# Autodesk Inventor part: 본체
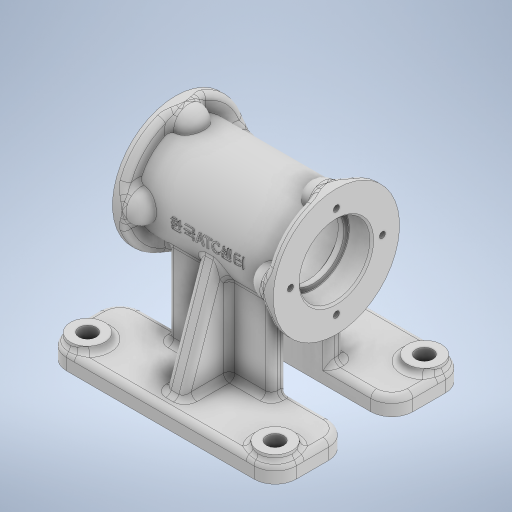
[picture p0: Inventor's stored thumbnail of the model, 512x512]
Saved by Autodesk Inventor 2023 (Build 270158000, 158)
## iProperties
Created: 2026-06
Part Number: 본체
Material: 일반
Document SubType Name: Modeling
Designer: home
Density: 1 g/cm^3
Appearance: 기본값
Author: home
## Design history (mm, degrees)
sketch "스케치1"
  geometry: L1 (0, 0)-(-75.914, 0); L2 (-42, 0)-(-42, 33); L3 (-42, 33)-(-37, 33); L4 (-37, 33)-(-37, 25); L5 (-37, 25)-(0, 25); L6 (0, 0)-(0, 52.72); L7 (37, 25)-(0, 25); L8 (37, 33)-(37, 25); L9 (42, 33)-(37, 33); L10 (42, 0)-(42, 33); L11 (-42, 18.5)-(-30, 18.5); L12 (-30, 18.5)-(-30, 16); L13 (-30, 16)-(-27, 16); L14 (-27, 16)-(-27, 20); L15 (-27, 20)-(0, 20); L16 (27, 20)-(0, 20); L17 (27, 16)-(27, 20); L18 (30, 16)-(27, 16); L19 (30, 18.5)-(30, 16); L20 (42, 18.5)-(30, 18.5); 1 further point
  constraints: 40 end point, 9 symmetric about line, 7 perpendicular, 3 point on line, 2 horizontal, 2 vertical
  dimensions: "d0" = 66 diameter of L3 L1; "d1" = 5 distance of L2.end L3.end; "d2" = 50 diameter of L5 L1; "d3" = 42 distance between parallel lines of L6 L2; "d4" = 12 distance of L11.start L11.end; "d6" = 27 distance of L14.end L15.end; "d7" = 37 diameter of L11 L1; "d8" = 32 diameter of L13 L1; "d9" = 40 diameter of L15 L1
revolve "회전1" sketch "스케치1" stored, may be unused: angle "d10" = 90 deg
sketch "스케치2"
  geometry: L1 (37, 25)-(-37, 25) reference; L2 (-37, 33)-(-37, -33) reference; L3 (-37.099, 34.348)-(-37, 34.348); L4 (-37, 33)-(-35, 33); L5 (-27, 25)-(-27, 25); A1 r 8 centre (-35, 25) between (-27, 25) and (-35, 33); 2 further points
  constraints: 6 end point, 2 perpendicular, 2 point on circle, 2 point on line, 2 tangent, 1 centre point, 1 horizontal
  dimensions: "d14" = 8 radius of A1 (derived); "d15" = 10 distance from line of L2 L5.end
revolve "회전2" sketch "스케치2" stored, may be unused: angle "d16" = 210 deg
node "작업 평면1"
sketch "스케치3"
  geometry: L1 (60, -50)-(-60, -50); L2 (-60, -50)-(-60, -11); L3 (-60, -11)-(60, -11); L4 (60, -11)-(60, -50); 2 further points
  constraints: 8 end point, 2 parallel, 1 horizontal, 1 midpoint, 1 perpendicular, 1 vertical alignment
  dimensions: "d21" = 120 distance of L1.start L1.end; "d22" = 39 distance of L3.end L1.start; "d41" = 50 distance from line of point (0, 0) L1
extrude "돌출1" join sketch "스케치3" distance "d23" = 9; taper "d24" = 0 deg
sketch "스케치4"
  geometry: L1 (60, 11)-(60, 50) reference; L2 (60, 50)-(-60, 50) reference; C1 r 9 at (49, 39); 1 further point
  constraints: 1 centre point
  dimensions: "d27" = 11 distance from line of L1 C1.centre; "d28" = 11 distance from line of L2 C1.centre; "d29" = 18 diameter of C1
extrude "돌출2" join sketch "스케치4" distance "d30" = 3; taper "d31" = 0 deg
fillet "모깎기1" dims "d32" = 11
sketch "스케치5"
  geometry: C1 r 9 at (0, 0) reference; 2 further points
  constraints: 1 coincident
hole "구멍1" sketch "스케치5" at (0, 0) diameter "d33" = 9; stored, may be unused: countersink angle "d37" = 90 deg, drill point angle "d39" = 0 deg; dims "d34" = 8, "d35" = 4, "d36" = 2, "d38" = 10
fillet "모깎기2" dims "d40" = 11
sketch "스케치7"
  geometry: L1 (0, 39)-(98, 39) reference; L2 (0, 39)-(98, 39) reference; L3 (22, 39)-(76, 39); L4 (76, 39)-(76, 31); L5 (76, 31)-(22, 31); L6 (22, 31)-(22, 39); 4 further points
  constraints: 8 end point, 2 parallel, 1 horizontal, 1 midpoint, 1 perpendicular, 1 point on line, 1 vertical alignment
  dimensions: "d47" = 8 distance of L5.end L3.start; "d48" = 54 distance of L4.end L5.end
extrude "돌출4" join sketch "스케치7" stored distance "d49" = 10; taper "d50" = 0 deg
sketch "스케치8"
  geometry: L1 (-61, -22)-(-61, -39) reference; L2 (-61, -19)-(-16.248, -19) reference; L3 (-6.346, -24.181)-(-61, -43); L4 (-61, -30)-(-61, -48) reference; L5 (-70, -50)-(-61, -50) reference; L6 (-61, -43)-(-61, -19); L7 (-61, -11)-(-61, -22) reference; L8 (-61, -19)-(-61, -11) reference; L9 (-61, -19)-(-16.248, -19); A1 r 25 centre (0, 0) between (-7.897, 23.72) and (-23.72, 7.897) reference; A2 r 25 centre (0, 0) between (-22.45, -11) and (-16.248, -19) reference; A3 r 25 centre (0, 0) between (-6.346, -24.181) and (-7.897, 23.72); 5 further points
  constraints: 6 end point, 2 point on circle, 1 centre point, 1 coincident, 1 collinear, 1 point on line
  dimensions: "d52" = 7 distance from line of L5 L3.end; "d53" = 19 deg angle of L2 L3
extrude "돌출5" join sketch "스케치8" stored distance "d54" = 10; taper "d55" = 0 deg
sketch "스케치9"
  geometry: L1 (0, 0)-(0, 24); C1 r 33 at (0, 0) reference
  constraints: 2 end point, 1 vertical
  dimensions: "d56" = 24 distance of L1.start L1.end
hole "구멍2" sketch "스케치9" at (0, 24) diameter "d57" = 3.242; stored, may be unused: countersink angle "d61" = 90 deg, drill point angle "d63" = 118 deg; dims "d58" = 8, "d59" = 4, "d60" = 2, "d62" = 10
fillet "모깎기4" dims "d67" = 3
sketch "스케치10"
  geometry: L1 (-64, 11)-(-22.45, 11) reference; L2 (-50, 11)-(-50, -11); L3 (-64, -11)-(-22.45, -11) reference; L4 (-50, 11)-(-22.45, 11); L5 (-22.45, -11)-(-50, -11); L6 (-70, 11)-(-70, 22) reference; A1 r 25 centre (0, 0) between (-16.248, 19) and (-22.45, 11) reference; A2 r 25 centre (0, 0) between (-22.45, -11) and (-16.248, -19) reference; 3 further points
  constraints: 6 end point, 2 point on line, 1 coincident, 1 collinear, 1 horizontal, 1 vertical, 3 other
  dimensions: "d68" = 20 distance between parallel lines of L6 L2
extrude "돌출6" join sketch "스케치10" stored distance "d69" = 10; taper "d70" = 0 deg
fillet "모깎기5" dims "d71" = 3
fillet "모깎기6" dims "d72" = 3
fillet "모깎기7" dims "d73" = 3
fillet "모깎기8" dims "d74" = 3
fillet "모깎기9" dims "d75" = 3
fillet "모깎기10" dims "d76" = 3
fillet "모깎기11" dims "d77" = 3
node "작업 평면2"
sketch "스케치11"
  geometry: L1 (-12.769, 7.739)-(12.769, 7.739); L2 (12.769, 7.739)-(12.769, -7.739); L3 (12.769, -7.739)-(-12.769, -7.739); L4 (-12.769, -7.739)-(-12.769, 7.739); 3 further points
  constraints: 2 midpoint, 1 horizontal alignment, 1 vertical alignment, 2 other
feature "엠보싱1" sketch "스케치11" dims "d0" = 66, "d1" = 5, "d2" = 50, "d3" = 42, "d4" = 12, "d6" = 27, "d7" = 37, "d8" = 32, "d9" = 40, "d80" = 0.5, "d81" = 0
fillet "모깎기13" dims "d82" = 0.3
fillet "모깎기14" dims "d83" = 3
chamfer "모따기1" distance "d84" = 1; stored, may be unused: second distance "d85" = 2, angle "d86" = 45 deg
node "솔리드1"
pattern_circular "원형 패턴1" dims angle "d18" = 360 deg
mirror "미러1"
mirror "미러2"
mirror "미러3"
mirror "미러4"
mirror "미러5"
pattern_circular "원형 패턴2" dims angle "d65" = 360 deg
mirror "미러6"
feature "A9D066F2-1C7D-4E18-AEED-F7BC21143FA4" dims "d33" = 9, "d34" = 8, "d35" = 4, "d36" = 2, "d37" = 90 deg, "d38" = 10, "d39" = 0
other parameters: "d79" = 72.75
